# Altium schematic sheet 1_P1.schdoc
size 309 x 223 mm; Symbol: Sheet-Symbol_A4; Device: Sheet-Symbol_A4; @Project Name: Project Name; @Page Count: 3; @Update Date: 2021.11.05; @Create Date: 2024-10-03; @Schematic Name: Schematic Name; @Page No: 1; @Page Name: P1; Company: EasyEDA.com; Reviewed: EasyEDA; Version: V0.1; Page Size: A4; Part Number: JLCPCB-002; Drawn: EasyEDA; @Board Name: IMUFINAL; @Create Time: 10:32:59; @Update Time: 10:43:11
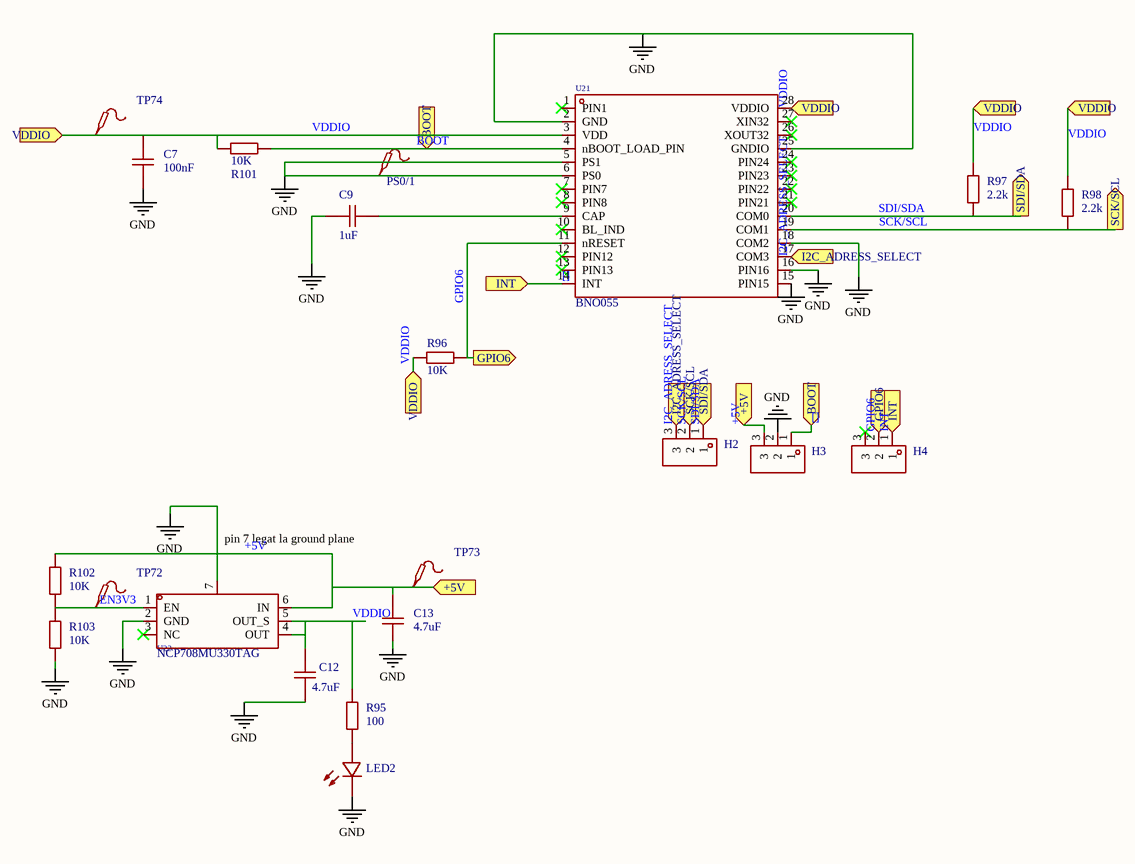
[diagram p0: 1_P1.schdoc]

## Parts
C7  100nF  [Cbst2]  (value not drawn)
C9  1uF  [C9]  (value not drawn)
C12  4.7uF  [C9]  (value not drawn)
C13  4.7uF  [C9]  (value not drawn)
H2  HDR-M_2.54_1x3P  [HDR-TH_3P-P2.54-V-M]  (value not drawn)
H3  HDR-M_2.54_1x3P  [HDR-TH_3P-P2.54-V-M]  (value not drawn)
H4  HDR-M_2.54_1x3P  [HDR-TH_3P-P2.54-V-M]  (value not drawn)
LED2  TLMS1100-GS08  [LED2 RED]  (value not drawn)
PS0/1  Test-Point  [Test-Point-0.5mm]  (value not drawn)
R95  100  [Rtrip]  (value not drawn)
R96  10K  [0805 dany2]  (value not drawn)
R97  2.2k  [0805 dany2]  (value not drawn)
R98  2.2k  [0805 dany2]  (value not drawn)
R101  10K  [0805 dany2]  (value not drawn)
R102  10K  [R0603]  (value not drawn)
R103  10K  [R0603]  (value not drawn)
TP72  Test-Point  [Test-Point-0.5mm]  (value not drawn)
TP73  Test-Point  [Test-Point-0.5mm]  (value not drawn)
TP74  Test-Point  [Test-Point-0.5mm]  (value not drawn)
U21  BNO055  [LGA-28_L5.2-W3.8-P0.50-BL]  (value not drawn)
U22  NCP708MU330TAG  [DFN-6_L3.0-W3.0-P0.95-LS3.1-BL-EP]  (value not drawn)

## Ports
+5V (in), BOOT (in), GPIO6 (in), GPIO6 (out), I2C_ADRESS_SELECT (in), INT (in), SCK/SCL (in), SCK/SCL (out), SDI/SDA (in), SDI/SDA (out), VDDIO (in)

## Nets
GND: C7.1 C9.1 C12.1 C13.1 H3.2 LED2.1(C) PS0/1.1 R103.2 U21.2(GND) U21.5(PS1) U21.6(PS0) U21.15(PIN15) U21.16(PIN16) U21.18(COM2) U21.25(GNDIO) U22.2(GND) U22.7(PAD)
+5V: C13.2 H3.3 R102.1 TP73.1 U22.6(IN) ; port +5V
[]: H3.1 H4.1 R101.2 U21.4(nBOOT_LOAD_PIN) U21.14(INT) ; port INT, port BOOT  [also labelled BOOT, INT]
EN3V3: R102.2 R103.1 TP72.1 U22.1(EN)
GPIO6: H4.2 R96.1 U21.11(nRESET) ; port GPIO6
I2C_ADRESS_SELECT: H2.3 U21.17(COM3) ; port I2C_ADRESS_SELECT
SCK/SCL: H2.2 R98.1 U21.19(COM1) ; port SCK/SCL
SDI/SDA: H2.1 R97.2 U21.20(COM0) ; port SDI/SDA
VDDIO: C7.2 C12.2 R95.2 R96.2 R97.1 R98.2 R101.1 TP74.1 U21.3(VDD) U21.28(VDDIO) U22.4(OUT) U22.5(OUT_S) ; port VDDIO
NetC9_2: C9.2 U21.9(CAP)
NetLED2_2: LED2.2(A) R95.1

Not connected (* = marked no-connect by the designer): H4 3*; U21 1(PIN1)* 7(PIN7)* 8(PIN8)* 10(BL_IND)* 12(PIN12)* 13(PIN13)* 21(PIN21)* 22(PIN22)* 23(PIN23)* 24(PIN24)* 26(XOUT32)* 27(XIN32)*; U22 3(NC)*

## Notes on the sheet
- pin 7 legat la ground plane

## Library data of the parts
C7 C9 C12 C13 = CAP_0201: Symbol: CAP; Convert to PCB: yes
H2-H4 = HDR-M_2.54_1x3P: Symbol: PZ254V-11-03P_C2937625; Convert to PCB: yes
LED2 = TLMS1100-GS08: Emitted Color:Red Forward Voltage (VF):2.1V Forward Voltage (VF):2.1V Forward Current:20mA Dominant Wavelength:633nm Dominant Wavelength:633nm Peak Wavelength:645nm Luminous Intensity:63mcd Luminous Intensity:63mcd Viewing Angle:160°; Manufacturer: VISHAY(威世); Add into BOM: yes; Emitted Color: Red; Forward Voltage (VF): 2.1V; Forward Current: 20mA; Dominant Wavelength: 633nm; Peak Wavelength: 645nm; Luminous Intensity: 63mcd; Viewing Angle: 160°
PS0/1 TP72-TP74 = Test-Point: Test Point 测试点; Add into BOM: yes
R95-R98 R101-R103 = Res_0201: Symbol: Res; Convert to PCB: yes
U21 = BNO055: Manufacturer: Bosch(博世); Add into BOM: yes
U22 = NCP708MU330TAG: Output Type: Maximum Input Voltage:5.5V Output Voltage:3.3V Output Voltage:3.3V MAX Output Current:1A Power Supply Rejection Ratio (PSRR):70dB@(1kHz) Dropout Voltage:330mV@(1A) Output Polarity:Positive electrode Number of Outputs:1; Manufacturer: onsemi(安森美); Add into BOM: yes; Maximum Input Voltage: 5.5V; Output Voltage: 3.3V; Number of Outputs: 1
